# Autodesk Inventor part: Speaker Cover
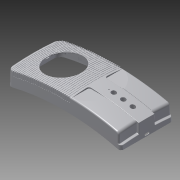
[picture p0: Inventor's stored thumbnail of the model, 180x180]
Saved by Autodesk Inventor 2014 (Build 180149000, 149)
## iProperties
Created: 2009-01
Part Number: Speaker Cover
Document SubType Name: Modeling
Designer: linb
Density: 1 g/cm^3
Material: Generic
Appearance: Default
Author: linb
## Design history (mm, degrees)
node "工作平面1"
node "工作平面2"
node "工作平面3"
node "工作平面4"
feature "放样曲面1" dims "d8" = 0, "d9" = 90 deg, "d10" = 0, "d11" = 90 deg, "d12" = 0, "d13" = 90 deg, "d14" = 0, "d15" = 90 deg
node "工作平面5"
node "工作平面6"
feature "灌注1"
feature "拔模斜度2" dims angle "d124" = 1 deg
sketch "草图6"
  geometry: L1 (-120, -30)-(120, -30) reference; A1 r 470 centre (0, -484.423) between (120, -30) and (-120, -30)
  constraints: 2 point on circle, 1 centre point
  dimensions: "d32" = 470 radius of A1
extrude "拉伸1" cut sketch "草图6" stored distance "d27" = 10; taper "d28" = 0 deg
feature "偏移曲面2" dims "d125" = 20, "d126" = 20
feature "延伸2" dims "d127" = 30.5
sketch "草图11"
  geometry: L1 (125, 67)-(115, 67); L2 (115, 67)-(115, 17); L3 (115, 17)-(125, 17); L4 (125, 17)-(125, 67); L5 (125, -67)-(115, -67); L6 (115, -67)-(115, -17); L7 (115, -17)-(125, -17); L8 (125, -17)-(125, -67); 1 further point
  constraints: 16 end point, 4 parallel, 2 equal length, 2 horizontal, 2 perpendicular, 1 collinear
  dimensions: "d84" = 34 distance between parallel lines of L7 L3; "d85" = 17 distance from line of point (0, 0) L7; "d86" = 10 distance of L5.start L5.end; "d87" = 115 distance from line of point (0, 0) L6; "d88" = 50 distance of L3.end L1.start
extrude "拉伸6" cut sketch "草图11" stored distance "d89" = 50; taper "d90" = 0 deg
node "工作平面9"
  node "工作点1"
sketch "草图16"
  geometry: L1 (-1, -12.776)-(59, -12.776); L2 (59, -12.776)-(59, 37.224); L3 (59, 37.224)-(-1, 37.224); L4 (-1, 37.224)-(-1, -12.776); L5 (-1, 71.224)-(59, 71.224); L6 (59, 71.224)-(59, 121.224); L7 (59, 121.224)-(-1, 121.224); L8 (-1, 121.224)-(-1, 71.224); 1 further point
  constraints: 16 end point, 4 parallel, 3 collinear, 2 horizontal, 2 perpendicular
  dimensions: "d129" = 15 distance from line of L4 point (-16, 54.224); "d130" = 60 distance of L2.end L3.end; "d131" = 50 distance of L3.end L1.start; "d132" = 34 distance between parallel lines of L5 L3; "d133" = 17 distance from line of L3 point (-16, 54.224)
extrude "拉伸10" cut sketch "草图16" stored distance "d134" = 10; taper "d135" = 0 deg
feature "抽壳1" dims "d31" = 2
feature "偏移曲面3" dims "d136" = 0.5, "d137" = 0.5
feature "延伸3" dims "d138" = 20
sketch "草图7"
  geometry: L1 (15, -18)-(135, -18); L2 (135, -18)-(135, -17); L3 (135, -17)-(15, -17); L4 (15, -17)-(15, -18); L5 (135, 18)-(15, 18); L6 (15, 18)-(15, 17); L7 (15, 17)-(135, 17); L8 (135, 17)-(135, 18); L9 (15, -60)-(16, -60); L10 (16, -60)-(16, -17); L11 (16, -17)-(15, -17); L12 (15, -17)-(15, -60); L13 (15, 17)-(16, 17); L14 (16, 17)-(16, 60); L15 (16, 60)-(15, 60); L16 (15, 60)-(15, 17); 1 further point
  constraints: 32 end point, 8 parallel, 4 equal length, 4 horizontal, 4 perpendicular, 2 collinear, 1 point on line
  dimensions: "d34" = 34 distance between parallel lines of L7 L3; "d35" = 17 distance from line of point (0, 0) L3; "d36" = 15 distance from line of L4 point (0, 0); "d37" = 1 distance of L1.end L2.end; "d38" = 120 distance of L5.start L5.end; "d42" = 60 distance from line of point (0, 0) L9; "d45" = 60 distance from line of L15 point (0, 0)
extrude "拉伸2" cut sketch "草图7" stored distance "d40" = 10; taper "d41" = 0 deg
feature "拔模斜度3" dims angle "d139" = 1 deg
feature "拔模斜度4" dims angle "d140" = 1 deg
feature "删除面1"
feature "拔模斜度5" dims angle "d141" = 10 deg
feature "拔模斜度6" dims angle "d142" = 10 deg
sketch "草图10"
  geometry: C1 r 1 at (40, 0); C2 r 5 at (50, 0); C3 r 5 at (70, 0); C4 r 5 at (90, 0); 1 further point
  constraints: 4 centre point, 4 horizontal alignment, 2 equal radius
  dimensions: "d76" = 10 diameter of C2; "d77" = 2 diameter of C1; "d78" = 20 distance of C3.centre C4.centre; "d79" = 20 distance of C2.centre C3.centre; "d80" = 10 distance of C2.centre C1.centre; "d81" = 50 distance of point (0, 0) C2.centre
extrude "拉伸5" cut sketch "草图10" stored distance "d82" = 10; taper "d83" = 0 deg
node "工作平面7"
sketch "草图12"
  geometry: C1 r 7 at (90, 0); C2 r 5 at (90, 0); 1 further point
  constraints: 2 centre point, 1 coincident, 1 horizontal alignment
  dimensions: "d92" = 90 distance of point (0, 0) C1.centre; "d93" = 10 diameter of C2; "d94" = 14 diameter of C1
extrude "拉伸7" join sketch "草图12" stored distance "d95" = 50; taper "d96" = 0 deg
sketch "草图13"
  geometry: C1 r 7 at (70, 0); C2 r 5 at (70, 0); C3 r 7 at (50, 0); C4 r 5 at (50, 0); 1 further point
  constraints: 4 centre point, 2 coincident, 2 equal radius, 2 horizontal alignment
  dimensions: "d97" = 10 diameter of C2; "d98" = 14 diameter of C1; "d99" = 20 distance of C3.centre C1.centre; "d100" = 50 distance of point (0, 0) C3.centre
extrude "拉伸8" join sketch "草图13" stored distance "d101" = 50; taper "d102" = 0 deg
feature "移动面1" dims "d103" = 2
feature "拔模斜度1" dims angle "d104" = 2.5 deg
sketch "草图14"
  geometry: C1 r 3.5 at (100, 44); C2 r 3.5 at (100, -44); C3 r 2 at (100, 44); C4 r 2 at (100, -44); 1 further point
  constraints: 4 centre point, 2 coincident, 1 equal radius
  dimensions: "d105" = 100 horizontal distance of point (0, 0) C1.centre; "d106" = 100 horizontal distance of point (0, 0) C2.centre; "d107" = 88 distance of C1.centre C2.centre; "d108" = 44 vertical distance of point (0, 0) C1.centre; "d109" = 7 diameter of C1; "d110" = 4 diameter of C4; "d111" = 4 diameter of C3
extrude "拉伸9" join sketch "草图14" stored distance "d112" = 50; taper "d113" = 0 deg
feature "移动面2" dims "d114" = 10
node "工作平面10"
feature "拔模斜度7" dims angle "d144" = 2 deg
sketch "草图15"
  geometry: L1 (-5, 88.5)-(5, 88.5); L2 (5, 88.5)-(5, 87.5); L3 (5, 87.5)-(-5, 87.5); L4 (-5, 87.5)-(-5, 88.5); L5 (-0.5, 93)-(0.5, 93); L6 (0.5, 93)-(0.5, 83); L7 (0.5, 83)-(-0.5, 83); L8 (-0.5, 83)-(-0.5, 93); L9 (-5, 0.5)-(5, 0.5); L10 (5, 0.5)-(5, -0.5); L11 (5, -0.5)-(-5, -0.5); L12 (-5, -0.5)-(-5, 0.5); L13 (-0.5, 5)-(0.5, 5); L14 (0.5, 5)-(0.5, -5); L15 (0.5, -5)-(-0.5, -5); L16 (-0.5, -5)-(-0.5, 5); 2 further points
  constraints: 32 end point, 8 parallel, 5 equal length, 4 horizontal, 4 perpendicular, 2 collinear, 1 coincident
  dimensions: "d115" = 1 distance of L1.end L2.end; "d116" = 43.5 distance from line of point (100, 44) L3; "d117" = 43.5 distance from line of L9 point (100, 44); "d118" = 99.5 distance from line of point (100, 44) L6; "d119" = 10 distance of L9.start L9.end; "d120" = 10 distance of L13.end L14.end; "d121" = 95 distance from line of point (100, 44) L10; "d122" = 39 distance from line of point (100, 44) L13; "d123" = 39 distance from line of point (100, 44) L7
extrude "拉伸11" join sketch "草图15" stored distance "d145" = 10; taper "d146" = 0 deg
feature "拔模斜度8" dims angle "d147" = 5 deg
feature "偏移曲面4" dims "d148" = 2, "d149" = 2
extrude "拉伸12" cut sketch "草图14" stored distance "d150" = 10; taper "d151" = 0 deg
feature "拔模斜度9" dims angle "d152" = 1 deg
sketch "草图18"
  geometry: C1 r 1 at (184, 76); C2 r 1 at (128, 76); C3 r 1 at (128, 12); C4 r 1 at (184, 12); C5 r 2 at (184, 76); C6 r 2 at (128, 76); C7 r 2 at (128, 12); C8 r 2 at (184, 12); 1 further point
  constraints: 8 centre point, 6 equal radius, 4 coincident, 2 horizontal alignment, 2 vertical alignment
  dimensions: "d157" = 32 vertical distance of C2.centre point (100, 44); "d158" = 32 vertical distance of point (100, 44) C3.centre; "d159" = 56 distance of C4.centre C3.centre; "d160" = 28 horizontal distance of point (100, 44) C3.centre; "d161" = 2 diameter of C3; "d162" = 4 diameter of C7
extrude "拉伸14" join sketch "草图18" stored distance "d163" = 10; taper "d164" = 0 deg
feature "移动面3" dims "d165" = 20
feature "移动面4" dims "d166" = 25
feature "拔模斜度10" dims angle "d167" = 1 deg
feature "偏移曲面5" dims "d183" = 1, "d184" = 1
feature "偏移曲面6" dims "d185" = 1, "d186" = 1
feature "延伸4" dims "d187" = 12
feature "延伸5" dims "d188" = 12
sketch "草图20"
  geometry: L1 (-78, -25)-(-70, -25); L2 (-70, -25)-(-70, -10); L3 (-70, -10)-(-78, -10); L4 (-78, -10)-(-78, -25); L5 (-38, -21)-(-30, -21); L6 (-30, -21)-(-30, -6); L7 (-30, -6)-(-38, -6); L8 (-38, -6)-(-38, -21); L9 (30, -21)-(38, -21); L10 (38, -21)-(38, -6); L11 (38, -6)-(30, -6); L12 (30, -6)-(30, -21); L13 (70, -25)-(78, -25); L14 (78, -25)-(78, -10); L15 (78, -10)-(70, -10); L16 (70, -10)-(70, -25); 1 further point
  constraints: 32 end point, 8 parallel, 4 collinear, 4 equal length, 4 horizontal, 4 perpendicular
  dimensions: "d175" = 30 distance from line of L6 point (0, 0); "d176" = 70 distance from line of point (0, 0) L2; "d177" = 30 distance from line of point (0, 0) L12; "d178" = 70 distance from line of point (0, 0) L16; "d179" = 8 distance of L9.start L9.end; "d180" = 6 distance from line of point (0, 0) L7; "d181" = 10 distance from line of point (0, 0) L3; "d182" = 15 distance of L5.end L6.end
extrude "拉伸16" cut sketch "草图20" stored distance "d189" = 10; taper "d190" = 0 deg
feature "拔模斜度12" dims angle "d191" = 1 deg
node "工作平面11"
node "工作平面12"
sketch "草图21"
  geometry: L1 (118, -18)-(113.035, -18); L2 (113.035, -18)-(113, -16); L3 (113, -16)-(118, -16); L4 (118, -16)-(118, -18); L5 (113, -16)-(118, -10.041); L6 (118, -10.041)-(118, -16); 1 further point
  constraints: 12 end point, 1 collinear, 1 horizontal, 1 parallel, 1 perpendicular
  dimensions: "d194" = 16 distance from line of point (0, 0) L3; "d197" = 113 horizontal distance of point (0, 0) L2.end; "d200" = 5 distance of L2.end L3.end; "d201" = 2 distance of L3.end L1.start; "d206" = 50 deg angle of L3 L5; "d273" = 89 deg angle of L3 L2
extrude "拉伸17" join sketch "草图21" distance "d202" = 10; taper "d203" = 0 deg
extrude "拉伸19" join sketch "草图21" distance "d207" = 2; taper "d208" = 0 deg
pattern_linear "矩形阵列1" dims "d213" = 8
feature "偏移曲面7" dims "d217" = 0.5, "d218" = 0.5
feature "延伸6" dims "d221" = 12
feature "偏移曲面9" dims "d222" = 0.5, "d223" = 0.5
feature "曲面1"
mirror "镜像2"
sketch "草图19"
  geometry: L1 (3, -23)-(-3, -23); L2 (-3, -27)-(3, -27); L3 (0, -39.727)-(0, 28.361) reference; A1 r 2 centre (-3, -25) between (-3, -23) and (-3, -27); A2 r 2 centre (3, -25) between (3, -27) and (3, -23); 1 further point
  constraints: 4 end point, 4 point on circle, 4 tangent, 2 centre point, 1 horizontal, 1 parallel
  dimensions: "d168" = 25 vertical distance of point (0, 0) A1.centre; "d169" = 4 distance between parallel lines of L2 L1; "d170" = 6 distance of A2.centre A1.centre; "d269" = 3 distance from line of A2.centre L3 (derived)
extrude "拉伸15" cut sketch "草图19" stored distance "d172" = 10; taper "d173" = 0 deg
feature "拔模斜度11" dims angle "d174" = 1 deg
feature "修剪1"
feature "修剪2"
feature "偏移曲面11" dims "d224" = 10, "d225" = 10
feature "延伸7" dims "d226" = 15
feature "修剪3"
feature "修剪4"
feature "修剪5"
feature "修剪6"
feature "修剪7"
feature "修剪8"
feature "修剪9"
feature "修剪10" dims "d46" = 2, "d47" = 10, "d48" = 120, "d49" = 60, "d52" = 4
node "工作平面13"
feature "修剪11"
feature "修剪12"
feature "修剪13"
feature "修剪14"
feature "曲面3"
feature "修剪15"
feature "修剪16"
feature "缝合曲面1" dims "d270" = 0.254 (derived)
fillet "圆角1" dims "d229" = 10
fillet "圆角2" dims "d230" = 12
sketch "草图8" dims "d55" = 10
  geometry: L1 (10, -60)-(12, -60); L2 (12, -60)-(12, 60); L3 (12, 60)-(10, 60); L4 (10, 60)-(10, -60); L5 (6, 60)-(6, -60); L6 (8, -60)-(8, 60); L7 (6, -60)-(8, -60); L8 (8, 60)-(6, 60); L9 (2, 60)-(2, -60); L10 (4, -60)-(4, 60); L11 (2, -60)-(4, -60); L12 (4, 60)-(2, 60); L13 (-2, 60)-(-2, -60); L14 (0, -60)-(0, 60); L15 (-2, -60)-(0, -60); L16 (0, 60)-(-2, 60); L17 (-6, 60)-(-6, -60); L18 (-4, -60)-(-4, 60); L19 (-6, -60)-(-4, -60); L20 (-4, 60)-(-6, 60); L21 (-10, 60)-(-10, -60); L22 (-8, -60)-(-8, 60); L23 (-10, -60)-(-8, -60); L24 (-8, 60)-(-10, 60); L25 (-14, 60)-(-14, -60); L26 (-12, -60)-(-12, 60); L27 (-14, -60)-(-12, -60); L28 (-12, 60)-(-14, 60); L29 (-18, 60)-(-18, -60); L30 (-16, -60)-(-16, 60); L31 (-18, -60)-(-16, -60); L32 (-16, 60)-(-18, 60); L33 (-22, 60)-(-22, -60); L34 (-20, -60)-(-20, 60); L35 (-22, -60)-(-20, -60); L36 (-20, 60)-(-22, 60); L37 (-26, 60)-(-26, -60); L38 (-24, -60)-(-24, 60); L39 (-26, -60)-(-24, -60); L40 (-24, 60)-(-26, 60); L41 (-30, 60)-(-30, -60); L42 (-28, -60)-(-28, 60); L43 (-30, -60)-(-28, -60); L44 (-28, 60)-(-30, 60); L45 (-34, 60)-(-34, -60); L46 (-32, -60)-(-32, 60); L47 (-34, -60)-(-32, -60); L48 (-32, 60)-(-34, 60); L49 (-38, 60)-(-38, -60); L50 (-36, -60)-(-36, 60); L51 (-38, -60)-(-36, -60); L52 (-36, 60)-(-38, 60); L53 (-42, 60)-(-42, -60); L54 (-40, -60)-(-40, 60); L55 (-42, -60)-(-40, -60); L56 (-40, 60)-(-42, 60); L57 (-46, 60)-(-46, -60); L58 (-44, -60)-(-44, 60); L59 (-46, -60)-(-44, -60); L60 (-44, 60)-(-46, 60); L61 (-50, 60)-(-50, -60); L62 (-48, -60)-(-48, 60); L63 (-50, -60)-(-48, -60); L64 (-48, 60)-(-50, 60)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; 1 further point
  constraints: 256 end point, 2 horizontal, 2 parallel, 1 collinear, 1 perpendicular, 247 other
  dimensions: "d46" = 2 distance of L1.start L1.end; "d47" = 10 distance from line of L4 point (0, 0); "d48" = 120 distance of L1.end L2.end; "d49" = 60 distance from line of L1 point (0, 0); "d52" = 4 distance of L3.end L5.start
extrude "拉伸21" cut sketch "草图8" stored distance "d227" = 2; taper "d228" = 0 deg
feature "删除面2"
feature "偏移曲面12" dims "d231" = 4, "d232" = 4
feature "曲面4"
fillet "圆角3" dims "d233" = 4
fillet "圆角4" dims "d234" = 6
sketch "草图24" dims "d235" = 1, "d236" = 2.5
  geometry: L1 (120, -49.001)-(120, 49.001) reference; L2 (-120, 43.002)-(-120, -43.002) reference; L3 (119, 49.001)-(119, -49.001); L4 (-119, -43.002)-(-119, 43.002); L5 (117.5, 49.001)-(117.5, -49.001); L6 (-117.5, -43.002)-(-117.5, 43.002); 14 further points; 2 other entities
  constraints: 8 end point, 8 parallel, 42 other
extrude "拉伸22" cut sketch "草图24" stored distance "d237" = 2; taper "d238" = 0 deg
sketch "草图25" dims "d239" = 1.5
  geometry: L1 (0, 6)-(0, 0) reference; L2 (1.5, 6)-(1.5, 0); L3 (-3.662, 7.113)-(-2.568, 9.454); L4 (-3.687, -1.076)-(-2.568, -3.454); A1 r 2 centre (-2, 6) between (-2.325, 7.974) and (-3.662, 7.113); A2 r 2 centre (-2, 0) between (-3.687, -1.076) and (-2.325, -1.974); 2 further points; 2 other entities
  constraints: 6 end point, 4 point on circle, 2 centre point, 2 coincident, 2 parallel, 9 other
feature "曲面5"
feature "延伸8" dims "d242" = 5.75
extrude "拉伸23" cut sketch "草图25" stored distance "d243" = 2; taper "d244" = 0 deg
feature "删除面3"
fillet "圆角5" dims "d245" = 0.5
fillet "圆角6" dims "d246" = 1
fillet "圆角7" dims "d247" = 100
fillet "圆角8" dims "d248" = 1
fillet "圆角9" dims "d249" = 2.5
fillet "圆角10" dims "d250" = 1
fillet "圆角11" dims "d251" = 3
fillet "圆角12" dims "d252" = 2
fillet "圆角13" dims "d253" = 1
fillet "圆角14" dims "d254" = 1
fillet "圆角15" dims "d255" = 1
fillet "圆角16" dims "d256" = 0.5
fillet "圆角17" dims "d257" = 0.5
fillet "圆角18" dims "d258" = 0.5
fillet "圆角19" dims "d259" = 5
fillet "圆角20" dims "d260" = 7
fillet "圆角21" dims "d261" = 1
feature "灌注2"
  node "工作平面14"
sketch "草图17"
  geometry: C1 r 36.5 at (-55, 0); 1 further point
  constraints: 1 centre point, 1 horizontal alignment
  dimensions: "d153" = 73 diameter of C1; "d154" = 55 distance of C1.centre point (0, 0)
extrude "拉伸13" cut sketch "草图17" stored distance "d155" = 10; taper "d156" = 0 deg
sketch "草图26"
  geometry: C1 r 37.5 at (-55, 0); 1 further point
  constraints: 1 centre point, 1 horizontal alignment
  dimensions: "d263" = 55 distance of point (0, 0) C1.centre; "d264" = 75 diameter of C1
extrude "拉伸24" cut sketch "草图26" stored distance "d267" = 10; taper "d268" = 0 deg
fillet "Fillet22" dims "d271" = 0.5
fillet "Fillet23" dims "d272" = 2
body "Solid1"
sketch "草图1"
  geometry: A1 r 500 centre (0, -485.386) between (120, 0) and (-120, 0); 1 further point
  constraints: 2 horizontal alignment, 2 point on circle, 1 centre point
  dimensions: "d4" = 240 distance of A1.start A1.end; "d5" = 120 distance of A1.end point (0, 0); "d6" = 500 radius of A1
sketch "草图2"
  geometry: A1 r 500 centre (0, -485.386) between (120, 0) and (-120, 0) reference
sketch "草图3"
  geometry: A1 r 500 centre (0, -496.966) between (55, 0) and (-55, 0); 1 further point
  constraints: 2 point on circle, 1 centre point, 1 coincident
  dimensions: "d7" = 500 radius of A1
sketch "草图4"
  geometry: A1 r 500 centre (0, -496.966) between (55, 0) and (-55, 0) reference
body "Srf1"
sketch "草图5"
  geometry: L1 (-120, -55)-(120, -55) reference; L2 (-120, 55)-(-120, -55) reference; L3 (-120, 55)-(120, 55) reference; L4 (120, 55)-(120, -55) reference
node "边1"
body "Srf2"
body "Srf3"
body "Srf4"
node "工作平面8"
body "Srf5"
body "Srf6"
body "Srf7"
body "Srf8"
body "Srf9"
body "Srf10"
body "Srf12"
body "Srf13"
body "Srf15"
body "Srf16"
feature "放样曲面2" dims "d17" = 0, "d18" = 90 deg, "d19" = 0, "d20" = 90 deg
feature "边界嵌片1" dims "d21" = 0, "d22" = 0, "d23" = 0, "d24" = 0, "d25" = 0
body "Srf11"
feature "曲面2"
body "Srf14"
body "Srf17"
body "Srf18"
other parameters: "d0" = 55, "d1" = -55, "d33" = 36, "d60" = 75, "d91" = -2, "d128" = 16, "d143" = -3, "d193" = 15, "d262" = 1
